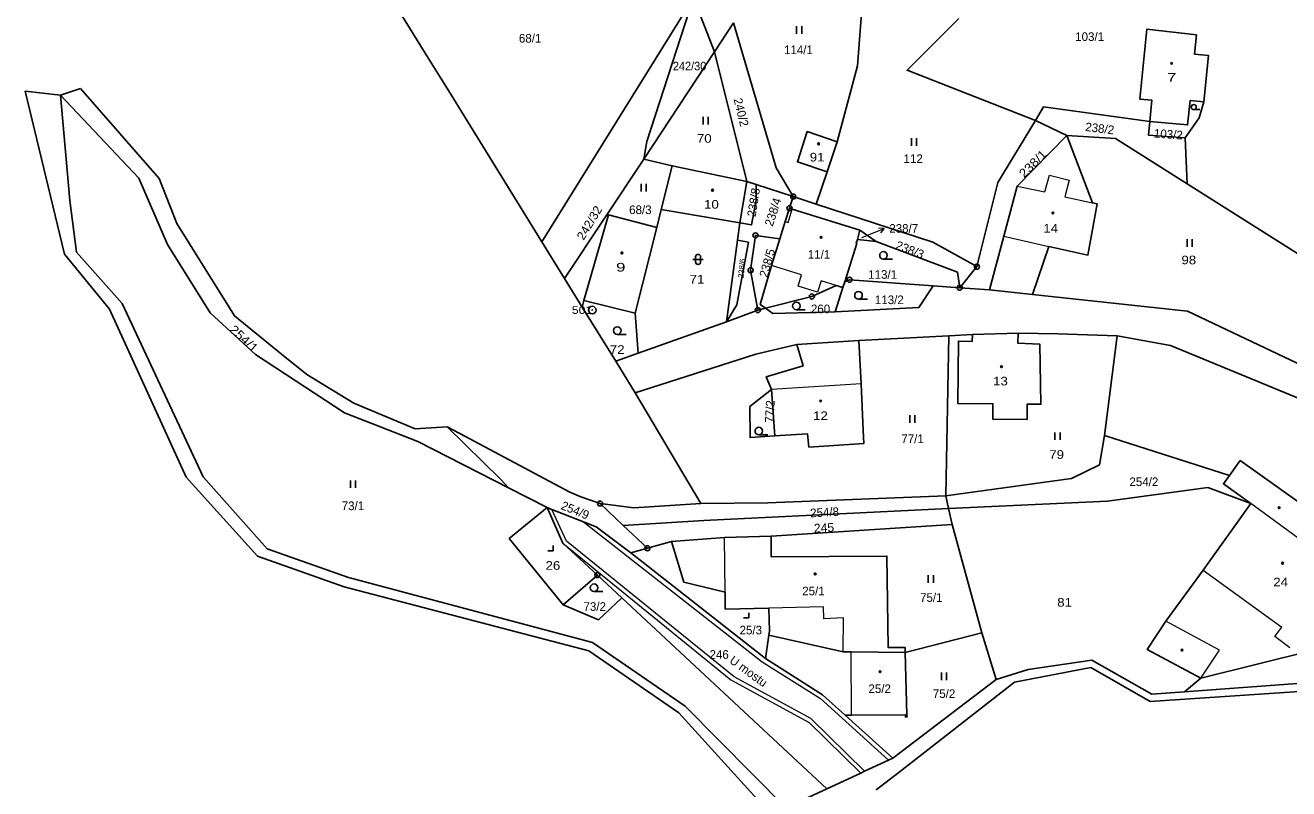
# Model space of a CAD drawing. Extents: x -632162 to -629607, y -1101195 to -1098670.
# Drawn here: x -632096.1 to -631847.3, y -1099551.6 to -1099401.2 of the extents above; entities that cross this region are included whole.
import ezdxf
from ezdxf.enums import TextEntityAlignment as Align

# ---------------------------------------------------------------- set-up
doc = ezdxf.new("R2010")
doc.units = 0
doc.header["$LTSCALE"] = 0.68
for name, color, linetype, lineweight in [('1', 7, 'Continuous', 25), ('3', 7, 'Continuous', 25), ('4', 7, 'Continuous', 13), ('5', 7, 'Continuous', 25), ('7', 7, 'Continuous', 13), ('8', 7, 'Continuous', 25)]:
    doc.layers.add(name, color=color, linetype=linetype, lineweight=lineweight)
doc.layers.add('2', color=7, linetype='Continuous')

msp = doc.modelspace()

# ---------------------------------------------------------------- linework, layer by layer
at = {"layer": '1'}
for p, q in [((-631960.36, -1099406.41), (-631964.49, -1099395.7)), ((-631956.6, -1099400.7), (-631960.36, -1099406.41)), ((-632089.14, -1099414.94), (-632096.11, -1099414.14)), ((-632085.21, -1099413.61), (-632089.14, -1099414.94)), ((-632069.73, -1099431.32), (-632085.21, -1099413.61)), ((-631890.97, -1099422.86), (-631897.15, -1099419.9)), ((-631955.4, -1099440.09), (-631954, -1099431.94)), ((-631952.19, -1099432.53), (-631952.18, -1099435.58)), ((-631837.61, -1099451.19), (-631867.3, -1099432.4)), ((-631944.86, -1099434.9), (-631945.6, -1099437.21)), ((-631971.76, -1099440.99), (-631970.86, -1099437.43)), ((-631955.87, -1099443.52), (-631955.4, -1099440.09)), ((-631931.72, -1099441.53), (-631928.54, -1099443.76)), ((-631989.92, -1099451.07), (-631994.37, -1099443.81)), ((-631951.83, -1099457.27), (-631953.27, -1099449.43)), ((-631908.68, -1099448.71), (-631912.08, -1099452.85)), ((-631935.09, -1099452.84), (-631934.73, -1099451.7)), ((-631935.09, -1099452.84), (-631936.58, -1099457.58)), ((-631906.18, -1099453.28), (-631897.76, -1099454.19)), ((-631986.43, -1099456.67), (-631986.11, -1099455.39)), ((-631951.83, -1099457.27), (-631957.99, -1099459.57)), ((-631900.55, -1099461.81), (-631909.59, -1099462.08)), ((-631909.59, -1099462.08), (-631914.25, -1099462.32)), ((-631979.83, -1099467.3), (-631975.99, -1099473.55)), ((-631949.15, -1099472.9), (-631948.47, -1099482.06)), ((-632013, -1099480.25), (-632019.34, -1099480.64)), ((-631993.3, -1099496.17), (-632000.93, -1099492.27)), ((-631986.72, -1099494.05), (-631982.9, -1099495.39)), ((-631914.78, -1099493.84), (-631914.29, -1099496.33)), ((-631982.9, -1099495.39), (-631978.33, -1099499.71)), ((-631978.33, -1099499.71), (-631973.59, -1099504.19)), ((-631913.55, -1099499.5), (-631949.22, -1099501.82)), ((-631973.59, -1099504.19), (-631976.87, -1099505.09)), ((-631968.82, -1099502.87), (-631973.59, -1099504.19)), ((-631976.87, -1099505.09), (-631950.31, -1099525.91)), ((-631978.6, -1099513.97), (-631983.43, -1099509.47)), ((-631949.68, -1099521.29), (-631950.31, -1099525.91)), ((-631867.81, -1099532.47), (-631842.9, -1099530.65)), ((-631934.67, -1099537.07), (-631933.36, -1099537.06))]:
    msp.add_line(p, q, dxfattribs=at)
for points in [[(-632086.36, -1099291.21), (-632073.13, -1099313.62), (-632058.06, -1099339.17), (-632051.08, -1099351.01), (-632038.22, -1099372.81), (-632017.33, -1099406.64), (-632014.07, -1099411.91), (-632013.3, -1099413.15), (-631994.37, -1099443.81), (-631964.49, -1099395.7)], [(-631930.9, -1099391.85), (-631932.22, -1099409.18), (-631936.19, -1099424.15), (-631938.21, -1099430.02), (-631940.35, -1099436.37)], [(-631964.49, -1099395.7), (-631973.67, -1099424.03), (-631974.28, -1099427.52)], [(-631956.6, -1099400.7), (-631948.25, -1099429.27), (-631944.86, -1099434.9), (-631940.35, -1099436.37)], [(-631912.23, -1099399.85), (-631922.45, -1099410.03), (-631897.15, -1099419.9)], [(-631864, -1099416.23), (-631863.1, -1099407.09), (-631865.82, -1099406.84), (-631865.45, -1099403.06), (-631875.24, -1099401.95), (-631876.6, -1099415.7), (-631874.23, -1099415.92), (-631874.64, -1099420.1)], [(-631954, -1099431.94), (-631960.36, -1099406.41), (-631974.28, -1099427.52)], [(-632096.11, -1099414.14), (-632088.38, -1099446.23), (-632079.54, -1099457.05), (-632064.39, -1099490.2), (-632050.35, -1099505.75), (-632033.29, -1099511.8), (-631985.15, -1099524.42), (-631967.38, -1099536.57), (-631948.1, -1099557.91)], [(-632000.93, -1099492.27), (-632018.82, -1099483.13), (-632033.24, -1099477.49), (-632050.79, -1099466.02), (-632059.71, -1099457.81), (-632068.08, -1099444.33), (-632073.72, -1099431.27), (-632089.14, -1099414.94)], [(-632089.14, -1099414.94), (-632087.35, -1099435.69), (-632086.01, -1099445.85), (-632077.01, -1099455.99), (-632061.08, -1099490.08), (-632048.45, -1099504.28), (-632032.48, -1099509.93), (-631984.42, -1099522.73), (-631966.13, -1099535.27), (-631946.34, -1099555.29), (-631938.25, -1099551.55), (-631978.6, -1099513.97)], [(-631874.64, -1099420.1), (-631867.19, -1099420.78), (-631866.72, -1099415.98), (-631864, -1099416.23)], [(-631864, -1099416.23), (-631864.95, -1099419.4), (-631867.68, -1099423.36), (-631867.3, -1099432.4)], [(-631897.15, -1099419.9), (-631895.55, -1099417.25), (-631874.64, -1099420.1)], [(-631938.21, -1099430.02), (-631944.05, -1099428.03), (-631942.09, -1099422.09), (-631936.19, -1099424.15)], [(-631908.68, -1099448.71), (-631904.54, -1099432.15), (-631897.15, -1099419.9)], [(-631874.64, -1099420.1), (-631874.9, -1099422.79), (-631867.68, -1099423.36)], [(-631890.97, -1099422.86), (-631900.76, -1099432.84), (-631903.38, -1099442.73), (-631906.18, -1099453.28)], [(-631897.76, -1099454.19), (-631894.5, -1099444.71), (-631886.83, -1099446.42), (-631885.03, -1099436.32), (-631885.94, -1099436.14), (-631890.97, -1099422.86)], [(-631867.3, -1099432.4), (-631881.39, -1099423.48), (-631890.97, -1099422.86)], [(-631968.7, -1099428.82), (-631974.28, -1099427.52), (-631989.92, -1099451.07), (-631986.43, -1099456.67)], [(-631954, -1099431.94), (-631968.7, -1099428.82), (-631970.86, -1099437.43), (-631955.4, -1099440.09)], [(-632045.68, -1099465.93), (-632054.93, -1099458.42), (-632066.24, -1099440.23), (-632069.73, -1099431.32)], [(-631954, -1099431.94), (-631952.19, -1099432.53), (-631944.86, -1099434.9)], [(-631952.18, -1099435.58), (-631953.07, -1099440.49), (-631955.4, -1099440.09)], [(-631940.35, -1099436.37), (-631917.34, -1099443.91), (-631908.68, -1099448.71)], [(-631971.76, -1099440.99), (-631981.26, -1099438.52), (-631986.11, -1099455.39)], [(-631945.6, -1099437.21), (-631946.43, -1099439.84), (-631947.52, -1099443.24)], [(-631931.72, -1099441.53), (-631945.09, -1099437.37), (-631945.6, -1099437.21)], [(-631986.11, -1099455.39), (-631976, -1099457.84), (-631971.76, -1099440.99)], [(-631934.73, -1099451.7), (-631932.37, -1099444.12), (-631932.46, -1099444.1), (-631932.24, -1099443.35), (-631931.72, -1099441.53)], [(-631976, -1099457.84), (-631975.42, -1099465.74), (-631957.99, -1099459.57), (-631955.87, -1099443.52)], [(-631955.87, -1099443.52), (-631953.7, -1099443.91), (-631955.97, -1099456.24), (-631957.99, -1099459.57)], [(-631953.27, -1099449.43), (-631952.29, -1099442.56), (-631947.52, -1099443.24)], [(-631947.52, -1099443.24), (-631949.15, -1099448.45), (-631951.39, -1099456.16), (-631950.34, -1099456.89), (-631941.2, -1099454.59), (-631936.39, -1099452.44), (-631935.09, -1099452.84)], [(-631912.08, -1099452.85), (-631912.53, -1099449.77), (-631928.54, -1099443.76), (-631932.24, -1099443.35)], [(-631934.73, -1099451.7), (-631933.78, -1099451.28), (-631917.33, -1099452.47)], [(-631917.33, -1099452.47), (-631920.1, -1099456.75), (-631936.58, -1099457.58)], [(-631906.18, -1099453.28), (-631912.08, -1099452.85), (-631917.33, -1099452.47)], [(-631897.76, -1099454.19), (-631867.24, -1099457.5), (-631839.23, -1099470.75)], [(-631986.43, -1099456.67), (-631979.83, -1099467.3), (-631975.42, -1099465.74)], [(-631936.58, -1099457.58), (-631938.99, -1099457.7), (-631948.87, -1099457.91), (-631950.34, -1099456.89), (-631951.83, -1099457.27)], [(-631909.59, -1099462.08), (-631909.64, -1099463.48), (-631912.34, -1099463.38), (-631912.47, -1099475.65), (-631905.53, -1099475.72), (-631905.56, -1099478.74), (-631898.82, -1099478.81), (-631898.79, -1099475.79), (-631896.07, -1099475.82), (-631896.33, -1099463.96), (-631900.63, -1099463.8), (-631900.55, -1099461.81)], [(-631881.1, -1099462.31), (-631892.78, -1099461.94), (-631900.55, -1099461.81)], [(-631944.13, -1099464.04), (-631952.25, -1099465.94), (-631975.99, -1099473.55), (-631963.08, -1099495.38)], [(-631963.08, -1099495.38), (-631949.86, -1099495.21), (-631914.78, -1099493.84), (-631914.25, -1099462.32), (-631931.97, -1099463.26)], [(-631944.13, -1099464.04), (-631942.91, -1099468.24), (-631950.17, -1099470.42), (-631949.15, -1099472.9)], [(-631948.47, -1099482.06), (-631942.04, -1099481.65), (-631941.78, -1099484.25), (-631930.97, -1099483.56), (-631931.09, -1099480.95), (-631931.51, -1099471.78), (-631931.97, -1099463.26), (-631944.13, -1099464.04)], [(-631914.78, -1099493.84), (-631890.08, -1099490.47), (-631884.52, -1099487.72), (-631883.56, -1099482), (-631881.1, -1099462.31)], [(-631796.05, -1099503.36), (-631842.87, -1099475.69), (-631870.58, -1099464.26), (-631881.1, -1099462.31)], [(-632019.34, -1099480.64), (-632031.43, -1099475.57), (-632040.68, -1099469.96), (-632045.68, -1099465.93)], [(-631948.47, -1099482.06), (-631953.37, -1099482.37), (-631953.41, -1099476.26), (-631949.15, -1099472.9)], [(-632000.93, -1099492.27), (-632002.44, -1099490.61), (-632013, -1099480.25)], [(-632013, -1099480.25), (-632009.56, -1099482.09), (-631988.97, -1099493.09), (-631986.72, -1099494.05)], [(-631883.56, -1099482), (-631858.96, -1099489.82), (-631856.86, -1099486.88)], [(-631856.86, -1099486.88), (-631841.79, -1099497.62), (-631842, -1099497.91), (-631838.48, -1099500.42), (-631839.12, -1099501.32), (-631835.67, -1099503.72), (-631835.73, -1099503.8), (-631829.57, -1099508.12)], [(-631854.76, -1099495.39), (-631860.14, -1099491.47), (-631858.96, -1099489.82)], [(-631854.76, -1099495.39), (-631863.2, -1099492.2), (-631883, -1099494.88), (-631914.29, -1099496.33), (-631913.55, -1099499.5)], [(-631993.3, -1099496.17), (-632000.79, -1099502.28), (-631990.15, -1099515.32), (-631983.43, -1099509.47)], [(-631976.87, -1099505.09), (-631983.66, -1099499.96), (-631986.19, -1099498.96), (-631992.39, -1099496.53), (-631993.3, -1099496.17)], [(-631983.43, -1099509.47), (-631990.21, -1099503.21), (-631993.3, -1099496.17)], [(-631982.9, -1099495.39), (-631976.25, -1099496.25), (-631963.08, -1099495.38)], [(-631914.29, -1099496.33), (-631962.48, -1099498.69), (-631978.33, -1099499.71)], [(-631864.57, -1099529.8), (-631875.15, -1099524.13), (-631871.46, -1099518.53), (-631864.16, -1099508.53), (-631854.76, -1099495.39)], [(-631922.8, -1099524.7), (-631907.75, -1099520.81), (-631913.55, -1099499.5)], [(-631949.22, -1099501.82), (-631958.37, -1099502.09), (-631968.82, -1099502.87)], [(-631968.82, -1099502.87), (-631966.44, -1099510.88), (-631958.29, -1099512.86), (-631958.27, -1099516.15), (-631949.67, -1099515.97), (-631949.57, -1099520.44), (-631949.68, -1099521.29)], [(-631922.8, -1099524.7), (-631922.83, -1099523.7), (-631926.14, -1099523.75), (-631926.43, -1099505.72), (-631949.2, -1099505.86), (-631949.22, -1099501.82)], [(-631978.6, -1099513.97), (-631983.22, -1099518.27), (-631990.15, -1099515.32)], [(-631842.9, -1099530.65), (-631832.18, -1099522.51), (-631828.64, -1099519.09), (-631823.37, -1099517.95), (-631827.9, -1099514.74), (-631842.4, -1099524.23), (-631864.57, -1099529.8)], [(-631949.68, -1099521.29), (-631935.01, -1099524.58), (-631933.44, -1099524.56), (-631922.8, -1099524.7)], [(-631934.67, -1099537.07), (-631925.27, -1099545.55), (-631904.93, -1099530.05), (-631907.75, -1099520.81)], [(-631950.31, -1099525.91), (-631939.12, -1099533.05), (-631934.67, -1099537.07)], [(-631933.36, -1099537.06), (-631922.77, -1099537.01), (-631922.76, -1099537.43), (-631922.46, -1099537.42), (-631922.47, -1099537), (-631922.8, -1099524.7)], [(-631904.93, -1099530.05), (-631898.6, -1099528.06), (-631886.07, -1099526.21), (-631874.22, -1099532.94), (-631867.81, -1099532.47), (-631864.57, -1099529.8)], [(-631928.51, -1099551.8), (-631924.83, -1099548.94), (-631924.32, -1099548.54), (-631901.26, -1099530.58), (-631886.23, -1099527.7), (-631874.54, -1099534.39), (-631823.61, -1099530.94), (-631764.34, -1099550.18), (-631746.33, -1099562.91)], [(-631938.25, -1099551.55), (-631931.56, -1099548.46), (-631930.83, -1099548.12), (-631926.09, -1099545.93), (-631925.27, -1099545.55)]]:
    msp.add_lwpolyline(points, dxfattribs=at)
at = {"layer": '3'}
for p, q in [((-631944.191, -1099402.86), (-631944.191, -1099401.36)), ((-631943.19, -1099402.86), (-631943.19, -1099401.36)), ((-631962.631, -1099420.69), (-631962.631, -1099419.19)), ((-631961.63, -1099420.69), (-631961.63, -1099419.19)), ((-631865.985, -1099417.78), (-631864.813, -1099417.78)), ((-631921.601, -1099424.92), (-631921.601, -1099423.42)), ((-631920.6, -1099424.92), (-631920.6, -1099423.42)), ((-631974.821, -1099433.9), (-631974.821, -1099432.4)), ((-631973.82, -1099433.9), (-631973.82, -1099432.4)), ((-631867.271, -1099444.78), (-631867.271, -1099443.28)), ((-631866.27, -1099444.78), (-631866.27, -1099443.28)), ((-631964.111, -1099446.781), (-631964.111, -1099447.782)), ((-631963.109, -1099447.782), (-631963.109, -1099446.781)), ((-631964.611, -1099447.281), (-631962.609, -1099447.281)), ((-631927.093, -1099447.25), (-631925.343, -1099447.25)), ((-631932.013, -1099455.11), (-631930.263, -1099455.11)), ((-631944.243, -1099457.2), (-631942.493, -1099457.2)), ((-631979.523, -1099462.06), (-631977.773, -1099462.06)), ((-631921.911, -1099479.48), (-631921.911, -1099477.98)), ((-631920.91, -1099479.48), (-631920.91, -1099477.98)), ((-631951.643, -1099481.84), (-631949.893, -1099481.84)), ((-631893.321, -1099482.85), (-631893.321, -1099481.35)), ((-631892.32, -1099482.85), (-631892.32, -1099481.35)), ((-632032.091, -1099492.31), (-632032.091, -1099490.81)), ((-632031.09, -1099492.31), (-632031.09, -1099490.81)), ((-631918.261, -1099510.98), (-631918.261, -1099509.48)), ((-631917.26, -1099510.98), (-631917.26, -1099509.48)), ((-631984.083, -1099512.71), (-631982.333, -1099512.71)), ((-631915.671, -1099530.16), (-631915.671, -1099528.66)), ((-631914.67, -1099530.16), (-631914.67, -1099528.66))]:
    msp.add_line(p, q, dxfattribs=at)
for points in [[(-631993.171, -1099504.67), (-631992.17, -1099504.67), (-631992.17, -1099503.67)], [(-631954.631, -1099517.87), (-631953.63, -1099517.87), (-631953.63, -1099516.87)]]:
    msp.add_lwpolyline(points, dxfattribs=at)
for centre, radius in [((-631865.9852, -1099417.2774), 0.5025), ((-631927.0929, -1099446.4998), 0.75), ((-631932.0129, -1099454.3598), 0.75), ((-631944.2429, -1099456.4498), 0.75), ((-631979.5229, -1099461.3098), 0.75), ((-631951.6429, -1099481.0898), 0.75), ((-631984.0829, -1099511.9598), 0.75)]:
    msp.add_circle(centre, radius, dxfattribs=at)
for centre, start, end in [((-631963.61, -1099446.7809), 0, 180), ((-631963.61, -1099447.7809), 180, 359.98789)]:
    msp.add_arc(centre, 0.5, start, end, dxfattribs=at)
at = {"layer": '4'}
for p, q in [((-631895.33, -1099433.99), (-631894.38, -1099430.71)), ((-631894.38, -1099430.71), (-631890.55, -1099431.67)), ((-631890.55, -1099431.67), (-631891.36, -1099434.96)), ((-631900.76, -1099432.84), (-631895.33, -1099433.99)), ((-631891.36, -1099434.96), (-631885.94, -1099436.14)), ((-631945.89, -1099440.01), (-631945.09, -1099437.37)), ((-631946.43, -1099439.84), (-631945.89, -1099440.01)), ((-631903.38, -1099442.73), (-631894.5, -1099444.71)), ((-631943.21, -1099450.33), (-631949.15, -1099448.45)), ((-631943.9, -1099452.53), (-631943.21, -1099450.33)), ((-631939.39, -1099451.51), (-631940.07, -1099453.73)), ((-631936.39, -1099452.44), (-631939.39, -1099451.51)), ((-631940.07, -1099453.73), (-631943.9, -1099452.53)), ((-631931.51, -1099471.78), (-631949.15, -1099472.9)), ((-631989.49, -1099502.8), (-631992.39, -1099496.53)), ((-631841.69, -1099504.93), (-631854.76, -1099495.39)), ((-631986.19, -1099498.96), (-631950.98, -1099526.53)), ((-631990.21, -1099503.21), (-631957.17, -1099530.12)), ((-631956.49, -1099529.52), (-631989.49, -1099502.8)), ((-631958.29, -1099512.86), (-631958.37, -1099502.09)), ((-631864.16, -1099508.53), (-631848.64, -1099519.73)), ((-631938.89, -1099515.74), (-631949.67, -1099515.97)), ((-631938.85, -1099518.09), (-631938.89, -1099515.74)), ((-631934.97, -1099517.87), (-631938.85, -1099518.09)), ((-631935.01, -1099524.58), (-631934.97, -1099517.87)), ((-631860.9, -1099524.28), (-631871.46, -1099518.53)), ((-631849.99, -1099521.59), (-631848.64, -1099519.73)), ((-631847.06, -1099523.77), (-631849.99, -1099521.59)), ((-631950.98, -1099526.53), (-631939.52, -1099533.81)), ((-631933.36, -1099537.06), (-631933.44, -1099524.56)), ((-631864.57, -1099529.8), (-631860.9, -1099524.28)), ((-631957.17, -1099530.12), (-631941.75, -1099538.48)), ((-631941.37, -1099537.72), (-631956.49, -1099529.52)), ((-631939.52, -1099533.81), (-631926.09, -1099545.93)), ((-631941.75, -1099538.48), (-631931.56, -1099548.46)), ((-631930.83, -1099548.12), (-631941.37, -1099537.72)), ((-631922.47, -1099537), (-631922.77, -1099537.01))]:
    msp.add_line(p, q, dxfattribs=at)
at = {"layer": '5'}
for centre in [(-631870.3368, -1099408.6492), (-631939.8768, -1099424.5192), (-631960.7568, -1099433.6492), (-631893.7168, -1099438.1392), (-631939.3868, -1099442.9292), (-631978.5968, -1099445.9992), (-631903.8568, -1099468.4092), (-631939.4668, -1099475.1792), (-631849.1668, -1099496.1792), (-631940.5468, -1099509.2392), (-631848.4868, -1099507.1292), (-631868.3068, -1099524.2392), (-631927.7568, -1099528.4892)]:
    msp.add_circle(centre, 0.175, dxfattribs=at)
at = {"layer": '7'}
msp.add_line((-631926.948, -1099441.186), (-631928.064, -1099441.097), dxfattribs=at)
msp.add_lwpolyline([(-631931.36, -1099442.97), (-631929.73, -1099442.31), (-631926.948, -1099441.186), (-631927.688, -1099442.025)], dxfattribs=at)
at = {"layer": '8'}
for centre, radius in [((-631944.86, -1099434.8999), 0.5), ((-631945.6, -1099437.2099), 0.5), ((-631944.86, -1099434.8999), 0.0303), ((-631945.6, -1099437.2099), 0.0303), ((-631952.29, -1099442.5599), 0.5), ((-631952.29, -1099442.5599), 0.0303), ((-631953.27, -1099449.4299), 0.5), ((-631953.27, -1099449.4299), 0.0303), ((-631908.68, -1099448.7099), 0.5), ((-631908.68, -1099448.7099), 0.0303), ((-631933.78, -1099451.2799), 0.5), ((-631933.78, -1099451.2799), 0.0303), ((-631941.2, -1099454.5899), 0.5), ((-631912.08, -1099452.8499), 0.5), ((-631912.08, -1099452.8499), 0.0303), ((-631984.45, -1099457.2598), 0.75), ((-631951.83, -1099457.2699), 0.5), ((-631941.2, -1099454.5899), 0.0303), ((-631984.45, -1099457.2598), 0.03), ((-631951.83, -1099457.2699), 0.0303), ((-631982.9, -1099495.3899), 0.5), ((-631982.9, -1099495.3899), 0.0303), ((-631973.59, -1099504.1899), 0.5), ((-631973.59, -1099504.1899), 0.0303), ((-631983.43, -1099509.4699), 0.5), ((-631983.43, -1099509.4699), 0.0303)]:
    msp.add_circle(centre, radius, dxfattribs=at)

# ---------------------------------------------------------------- texts
at = {"layer": '2'}
for s, p in [('68/1', (-631996.68, -1099404.57)), ('103/1', (-631886.49, -1099404.25)), ('114/1', (-631943.84, -1099406.84)), ('112', (-631921.239, -1099428.29)), ('68/3', (-631974.97, -1099438.35)), ('11/1', (-631939.78, -1099447.15)), ('113/1', (-631927.26, -1099451.1)), ('113/2', (-631925.94, -1099456.09)), ('260', (-631939.489, -1099457.88)), ('77/1', (-631921.37, -1099483.47)), ('254/2', (-631875.81, -1099491.93)), ('73/1', (-632031.58, -1099496.67)), ('25/1', (-631940.88, -1099513.45)), ('75/1', (-631917.68, -1099514.74)), ('73/2', (-631983.96, -1099516.51)), ('25/3', (-631953.22, -1099521.15)), ('246', (-631959.459, -1099525.96)), ('25/2', (-631927.84, -1099532.7)), ('75/2', (-631915.16, -1099533.67))]:
    msp.add_text(s, height=1.7, dxfattribs=at).set_placement(p, align=Align.CENTER)
for s, width, p in [('242/30', 0.95, (-631965.279, -1099410.04)), ('7', 1.45, (-631870.33, -1099412.25)), ('70', 1.15, (-631962.39, -1099424.3)), ('91', 1.15, (-631940.16, -1099427.99)), ('10', 1.15, (-631960.98, -1099437.28)), ('14', 1.15, (-631894.17, -1099442.01)), ('98', 1.15, (-631866.96, -1099448.24)), ('9', 1.45, (-631978.83, -1099449.67)), ('71', 1.15, (-631963.82, -1099452.03)), ('72', 1.15, (-631979.54, -1099465.89)), ('13', 1.15, (-631904.05, -1099472.1)), ('12', 1.15, (-631939.5, -1099478.93)), ('79', 1.15, (-631892.99, -1099486.56)), ('26', 1.15, (-631992.19, -1099508.42)), ('24', 1.15, (-631848.88, -1099511.69)), ('81', 1.15, (-631891.42, -1099515.68))]:
    msp.add_text(s, height=1.7, dxfattribs=dict(at, width=width)).set_placement(p, align=Align.CENTER)
for s, height, rotation, p in [('240/2', 1.7, 284, (-631955.9498, -1099418.4924)), ('238/2', 1.7, 353, (-631884.6046, -1099422.3114)), ('103/2', 1.7, 356, (-631871.0488, -1099423.4602)), ('238/8', 1.7, 81, (-631951.8462, -1099436.1745)), ('238/4', 1.7, 72, (-631948.0441, -1099438.2072)), ('238/3', 1.7, 339, (-631922.1906, -1099446.1709)), ('238/5', 1.7, 74, (-631949.1677, -1099448.2278)), ('238/6', 1.14, 84, (-631954.4484, -1099449.1196)), ('77/2', 1.7, 87, (-631948.6292, -1099477.2845)), ('254/9', 1.7, 338, (-631988.1354, -1099497.4836)), ('254/8', 1.7, 3, (-631938.646, -1099497.9463))]:
    msp.add_text(s, height=height, rotation=rotation, dxfattribs=at).set_placement(p, align=Align.CENTER)
for s, rotation, width, p in [('238/1', 45, 1.15, (-631897.068, -1099429.02)), ('242/32', 59, 1.05, (-631984.2652, -1099440.5058)), ('254/1', 317, 1.15, (-632053.6232, -1099463.5118)), ('245', 3, 1.05, (-631938.765, -1099500.9971))]:
    msp.add_text(s, height=1.7, rotation=rotation, dxfattribs=dict(at, width=width)).set_placement(p, align=Align.CENTER)
msp.add_text('238/7', height=1.7, dxfattribs=at).set_placement((-631925.95, -1099442.03))
at = {"layer": '7'}
msp.add_text('U mostu', height=1.7, rotation=324, dxfattribs=at).set_placement((-631954.1616, -1099529.1221), align=Align.CENTER)
at = {"layer": '8', "width": 1.2}
msp.add_text('501', height=1.5, dxfattribs=at).set_placement((-631984.45, -1099458.01), align=Align.RIGHT)

doc.saveas('drawing.dxf')
